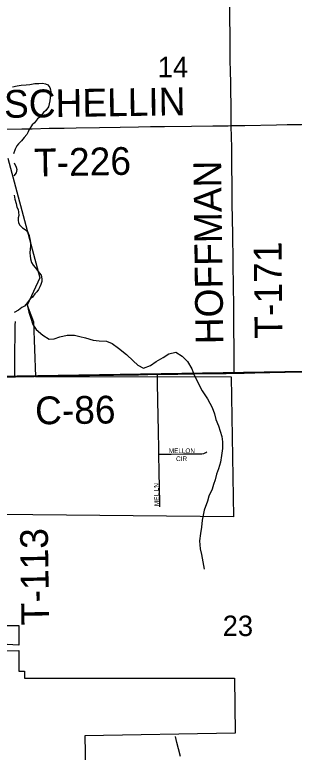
# Model space of a CAD drawing. Extents: x 1985906 to 2360102, y 891258 to 1222054.
# Drawn here: x 2130312 to 2133334, y 1037407 to 1045372 of the extents above; entities that cross this region are included whole.
import ezdxf

# ---------------------------------------------------------------- set-up
doc = ezdxf.new("R2010")
doc.units = 0
for name, color, linetype in [('GM_X_City_Street', 7, 'Continuous'), ('GM_X_City_Street_Text', 7, 'Continuous'), ('GM_X_Corporation', 7, 'Continuous'), ('GM_X_County_Road', 7, 'Continuous'), ('GM_X_County_Road_Text', 7, 'Continuous'), ('GM_X_Minor_River', 7, 'Continuous'), ('GM_X_Section', 7, 'Continuous'), ('GM_X_Section_Text', 7, 'Continuous'), ('GM_X_Township_Road', 7, 'Continuous'), ('GM_X_Township_Road_Text', 7, 'Continuous')]:
    doc.layers.add(name, color=color, linetype=linetype)

msp = doc.modelspace()

# ---------------------------------------------------------------- linework, layer by layer
at = {"layer": 'GM_X_City_Street'}
for points in [[(2130313.3, 1041461.3), (2130313.4, 1041490.7), (2130314.4, 1041702.1), (2130314.4, 1041779.2), (2130316.4, 1041865.1), (2130317.5, 1041969.8), (2130317.5, 1042021.1), (2130319.5, 1042060.7)], [(2131868.9, 1040626.9), (2131868.1, 1040678.9), (2131864.3, 1040875.4), (2131859.7, 1041203.1), (2131856.3, 1041399.6), (2131856.3, 1041448.8), (2131856.3, 1041489.5)], [(2130120.4, 1041459.6), (2130313.3, 1041461.3)], [(2130313.3, 1041461.3), (2130318.7, 1041461.3), (2130521, 1041465.5)], [(2131868.9, 1040626.9), (2131883.9, 1040626.9), (2132001.6, 1040626.9), (2132135.1, 1040629.2), (2132248.9, 1040630), (2132312.5, 1040630), (2132333.7, 1040630), (2132356.5, 1040633.9), (2132375.8, 1040642.9), (2132389.4, 1040652.1)], [(2131881.4, 1040056.5), (2131879.1, 1040105.7), (2131871.6, 1040433.2), (2131868.9, 1040626.9)]]:
    msp.add_lwpolyline(points, dxfattribs=at)
at = {"layer": 'GM_X_Corporation'}
for points in [[(2130238.5, 1043824.6), (2130582.4, 1042531.6), (2130447.3, 1042236.9), (2130514, 1042054.7), (2130535.1, 1041464.2), (2132651.3, 1041462.6), (2132676.9, 1039948.2), (2130143.9, 1039974.3)], [(2130163.3, 1038776.5), (2130355.5, 1038775.6), (2130355.4, 1038565.5), (2130166.1, 1038573.4)], [(2130171.7, 1038503.9), (2130355.4, 1038505.5), (2130355.4, 1038284.4), (2130415.4, 1038284.4), (2130415.4, 1038209.3), (2132686, 1038208.8), (2132695.6, 1037612.5), (2131070.6, 1037586.4), (2131098.6, 1036132.6)]]:
    msp.add_lwpolyline(points, dxfattribs=at)
at = {"layer": 'GM_X_County_Road'}
for points in [[(2130521, 1041465.5), (2130699.1, 1041467.9), (2130970.2, 1041472.6), (2131118.7, 1041475.1), (2131380.1, 1041480.3), (2131516.4, 1041482), (2131650.1, 1041483.7), (2131856.3, 1041489.5)], [(2131856.3, 1041489.5), (2131893.9, 1041490.5), (2132073.9, 1041492.2), (2132254, 1041494.6), (2132417.7, 1041496.4), (2132548.7, 1041498.4), (2132595.9, 1041498.9)], [(2132595.9, 1041498.9), (2132685.7, 1041499.9)], [(2132685.7, 1041499.9), (2132710.5, 1041499.9), (2132793.3, 1041502.4), (2132908.1, 1041504.9), (2133235.7, 1041511.3), (2133612.5, 1041519.4), (2133989.4, 1041526.6), (2134284.3, 1041532.4), (2134595.7, 1041538.9), (2134939.7, 1041545.8), (2135257, 1041551)]]:
    msp.add_lwpolyline(points, dxfattribs=at)
at = {"layer": 'GM_X_Minor_River'}
for points in [[(2130286.6, 1044592.3), (2130338.6, 1044605), (2130380.7, 1044609.6), (2130436.9, 1044616.3), (2130473, 1044618.8), (2130529.1, 1044629.6), (2130571.3, 1044628.2), (2130611.4, 1044632.7), (2130643.6, 1044627.1), (2130669.8, 1044615.4), (2130690.3, 1044587.6), (2130698.6, 1044561.7), (2130701, 1044537.6), (2130699.3, 1044509.5), (2130695.7, 1044475.4), (2130692.1, 1044443.2), (2130682.5, 1044411), (2130674.9, 1044378.8), (2130647.3, 1044336.3), (2130621.5, 1044315.9), (2130584, 1044267.3), (2130556.1, 1044246.8), (2130524.5, 1044204.3), (2130500.7, 1044181.9), (2130469.2, 1044133.4), (2130457.5, 1044107.1), (2130443.9, 1044076.9), (2130414.1, 1044046.4), (2130384.4, 1044011.9), (2130350.7, 1043979.3), (2130335, 1043955.1), (2130317.4, 1043920.7), (2130297.9, 1043868.3)], [(2130307.2, 1043772.2), (2130325.9, 1043726.3), (2130334.3, 1043700.3), (2130326.7, 1043664.1), (2130303, 1043631.7)], [(2130305.7, 1043423.1), (2130314.3, 1043379.1), (2130327, 1043333.2), (2130335.5, 1043295.2), (2130347.9, 1043269.3), (2130352.3, 1043241.2), (2130354.7, 1043205.2), (2130349.1, 1043177), (2130349.4, 1043152.9), (2130353.8, 1043124.9), (2130366.2, 1043099)], [(2130366.2, 1043099), (2130396.6, 1043071.3), (2130435.2, 1043043.8), (2130457.7, 1043012), (2130468, 1042988), (2130472.3, 1042964), (2130476.7, 1042936), (2130481.2, 1042904), (2130481.6, 1042869.9), (2130479.9, 1042843.8), (2130474.5, 1042797.6), (2130478.9, 1042769.5), (2130481.3, 1042737.5), (2130491.9, 1042695.5), (2130512.3, 1042667.7), (2130530.7, 1042641.9), (2130553.2, 1042614.1), (2130579.7, 1042582.3), (2130596.1, 1042558.5), (2130604.6, 1042520.5), (2130603, 1042492.4), (2130593.3, 1042460.2), (2130581.7, 1042431.9), (2130569.9, 1042405.7), (2130552.2, 1042379.4), (2130528.4, 1042357), (2130502.8, 1042320.6), (2130476.9, 1042302.2), (2130451.3, 1042263.7), (2130415.7, 1042223.1), (2130389.8, 1042208.7), (2130351.9, 1042182.2), (2130306.1, 1042157.5)], [(2130444.1, 1042255.5), (2130449.8, 1042225.9), (2130464.3, 1042160), (2130480.6, 1042106), (2130507.2, 1042026.1), (2130541.5, 1041974.3), (2130615.9, 1041912.8), (2130684.2, 1041869.2), (2130736.2, 1041871.7), (2130798, 1041894.1), (2130879.9, 1041912.8), (2130955.9, 1041911.3), (2131016, 1041897.8), (2131076.1, 1041882.2), (2131158.2, 1041858.8), (2131224.3, 1041851.3), (2131302.3, 1041845.9), (2131366.5, 1041822.3), (2131434.8, 1041772.8), (2131521.3, 1041703.3), (2131591.7, 1041635.8), (2131644, 1041588.1), (2131704.3, 1041554.5), (2131780, 1041585.1), (2131841.8, 1041625.6), (2131915.4, 1041670.2), (2131979.2, 1041710.8), (2132053, 1041729.4), (2132121.3, 1041683.8), (2132177.7, 1041628.2), (2132226.2, 1041548.4), (2132246.6, 1041490.5), (2132293.3, 1041394.7), (2132337.9, 1041309), (2132394.4, 1041225.3), (2132445.1, 1041131.5), (2132469.6, 1041061.6), (2132486, 1041001.7), (2132514.4, 1040931.8), (2132532.8, 1040875.9), (2132551.2, 1040815.9), (2132557.6, 1040757.9), (2132556.1, 1040687.8), (2132548.6, 1040613.7), (2132535.1, 1040539.5), (2132515.6, 1040469.2), (2132494, 1040411), (2132478.5, 1040350.8), (2132460.8, 1040298.6), (2132445.2, 1040248.4), (2132411.7, 1040172.1), (2132396, 1040119.9), (2132360.7, 1040023.5), (2132339.5, 1039915.2), (2132330, 1039837), (2132318.5, 1039768.8), (2132309, 1039690.7), (2132317.6, 1039604.6), (2132330, 1039544.6), (2132346.6, 1039462.7), (2132359.1, 1039384.7)], [(2132105.1, 1037360.2), (2132082.5, 1037444.1), (2132064, 1037514.1), (2132049.6, 1037576)]]:
    msp.add_lwpolyline(points, dxfattribs=at)
at = {"layer": 'GM_X_Section'}
for points in [[(2129997.9, 1046828.2), (2135136.8, 1046904.3), (2135234.2, 1041549.5), (2130109.5, 1041463.5)], [(2130109.5, 1041463.5), (2135234.2, 1041549.5), (2135365.6, 1036205), (2130202.8, 1036134.8)]]:
    msp.add_lwpolyline(points, close=True, dxfattribs=at)
at = {"layer": 'GM_X_Township_Road'}
for points in [[(2132652.8, 1044174.7), (2132649.7, 1044381.2), (2132647.6, 1044564.8), (2132646.2, 1044645.7), (2132644.3, 1044750), (2132642.4, 1044889.4), (2132639.3, 1045130.5), (2132626.2, 1046050.4), (2132624.6, 1046169.6), (2132622, 1046280.9)], [(2132652.8, 1044174.7), (2132797.6, 1044177.5), (2133142.4, 1044183.3), (2133257.2, 1044184.8), (2133412.6, 1044188.3), (2133880, 1044199.3), (2134097.3, 1044206.3), (2134355.7, 1044210.9), (2134552.6, 1044213.9), (2134716.8, 1044217.2), (2135075.6, 1044224.2), (2135203.7, 1044227.2)], [(2129666, 1044138), (2129694.6, 1044138), (2129797.2, 1044138.2), (2130042.4, 1044136.3), (2130206.3, 1044135.8), (2130386.7, 1044140), (2130498.4, 1044139.8), (2130682.1, 1044145.9), (2130846, 1044148.5), (2130977.2, 1044150.9), (2131227.1, 1044153.4), (2131453, 1044159.4), (2131650, 1044162.6), (2131781.1, 1044164.4), (2131930, 1044166.2), (2132223.4, 1044168.6), (2132453.2, 1044173), (2132619, 1044173.8), (2132652.8, 1044174.7)], [(2132685.7, 1041499.9), (2132685.6, 1041525), (2132685, 1041623.6), (2132680.4, 1042132.6), (2132679.6, 1042261.9), (2132676.9, 1042411.4), (2132668.7, 1043002.9), (2132663.6, 1043331.4), (2132657.6, 1043938.6), (2132652.9, 1044168.3), (2132652.8, 1044174.7)]]:
    msp.add_lwpolyline(points, dxfattribs=at)

# ---------------------------------------------------------------- texts
at = {"layer": 'GM_X_City_Street_Text'}
for s, rotation, p in [('MELLON', 0.00001, (2131976.5, 1040638.3)), ('CIR', 0.00001, (2132055.7, 1040552.3)), ('MEL LN', 91.12273, (2131870.5, 1040065.5))]:
    msp.add_text(s, height=50, rotation=rotation, dxfattribs=at).set_placement(p)
at = {"layer": 'GM_X_County_Road_Text'}
msp.add_text('C-86', height=300, rotation=0.69068, dxfattribs=at).set_placement((2130533.1, 1040948.1))
at = {"layer": 'GM_X_Section_Text'}
for s, p in [('14', (2131857.7, 1044696.4)), ('23', (2132559.5, 1038662.4))]:
    msp.add_text(s, height=221, rotation=0.00001, dxfattribs=at).set_placement(p)
at = {"layer": 'GM_X_Township_Road_Text'}
for s, rotation, p in [('SCHELLIN', 0.8523, (2130197.4, 1044258.1)), ('T-226', 1.12257, (2130523.1, 1043623.8)), ('HOFFMAN', 90.69909, (2132566.9, 1041814.9)), ('T-171', 90.5621, (2133205.6, 1041875.4)), ('T-113', 90.84126, (2130684.3, 1038781.5))]:
    msp.add_text(s, height=300, rotation=rotation, dxfattribs=at).set_placement(p)

doc.saveas('drawing.dxf')
